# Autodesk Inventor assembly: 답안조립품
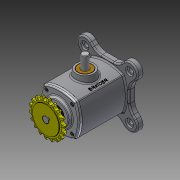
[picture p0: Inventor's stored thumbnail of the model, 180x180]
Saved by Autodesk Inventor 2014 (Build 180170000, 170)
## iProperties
Created: 2016-05
Part Number: 답안조립품
Document SubType Name: Assembly
Designer: HGY
Author: HGY
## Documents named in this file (11)
- C:\Users\Administrator\Desktop\460507V1025\답안조립품.iam
- C:\Users\Administrator\Desktop\460507V1025\1-본체.ipt
- C:\Users\Administrator\Desktop\460507V1025\M4x0.7x12.ipt
- C:\Users\Administrator\Desktop\460507V1025\베어링-6203.ipt
- C:\Users\Administrator\Desktop\460507V1025\부시.ipt
- C:\Users\Administrator\Desktop\460507V1025\스프로킷.ipt
- C:\Users\Administrator\Desktop\460507V1025\슬라이더.ipt
- C:\Users\Administrator\Desktop\460507V1025\오일실.ipt
- C:\Users\Administrator\Desktop\460507V1025\커버.ipt
- C:\Users\Administrator\Desktop\460507V1025\키5x5.ipt
- C:\Users\Administrator\Desktop\460507V1025\편심축.ipt
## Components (9 placed, 2 different names)
1. 1-본체:1
2. M4x0.7x12:1
3. M4x0.7x12:3
4. M4x0.7x12:4
5. M4x0.7x12:5
6. M4x0.7x12:2
7. M4x0.7x12:6
8. M4x0.7x12:7
9. M4x0.7x12:8
